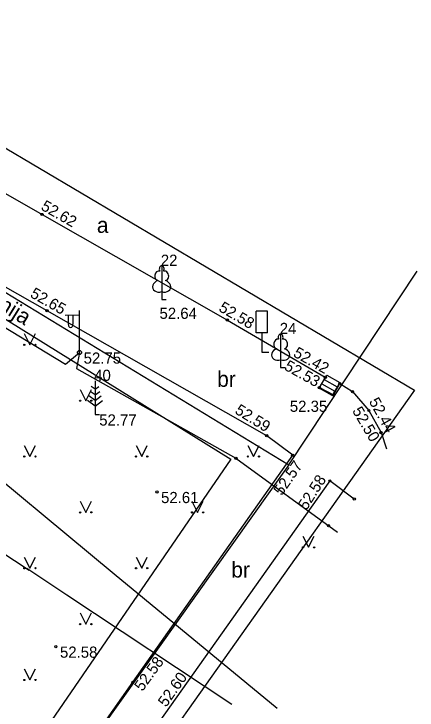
# Model space of a CAD drawing. Extents: x 619806 to 620082, y 405176 to 405386.
# Drawn here: x 620031.79 to 620049.82, y 405261.15 to 405292.31 of the extents above; entities that cross this region are included whole.
import ezdxf

# ---------------------------------------------------------------- set-up
doc = ezdxf.new("R2010")
doc.units = 0
for name, color, linetype in [('APGR_SARK_####_####_#', 7, 'Continuous'), ('APGR_SARK_IZNL_TKST_#', 7, 'Continuous'), ('APGS_ELEM_####_####_#', 7, 'Continuous'), ('APGS_VADP_ZSPR_####_#', 7, 'Continuous'), ('CELI_CAPM_####_####_#', 7, 'Continuous'), ('CELI_CMAL_####_####_#', 7, 'Continuous'), ('CELI_CSEG_####_TKST_#', 7, 'Continuous'), ('CELI_ELEM_####_####_#', 7, 'Continuous'), ('LKAN_ELEM_####_####_#', 7, 'Continuous'), ('LKAN_ELEM_PAST_TKST_#', 7, 'Continuous'), ('RAMI_UZMR_####_####_#', 7, 'Continuous'), ('RELJ_AATZ_####_TKST_#', 7, 'Continuous'), ('RELJ_ELEM_####_####_#', 7, 'Continuous'), ('ROBZ_PROJ_####_####_#', 7, 'Continuous'), ('ROBZ_UZMR_####_####_#', 7, 'Continuous'), ('SAKT_VADP_KABE_####_#', 7, 'Continuous'), ('TERT_DIAM_####_TKST_#', 7, 'Continuous'), ('TERT_ELEM_####_####_#', 7, 'Continuous'), ('UDTK_VADP_UDEN_####_#', 7, 'Continuous')]:
    doc.layers.add(name, color=color, linetype=linetype)

msp = doc.modelspace()

# ---------------------------------------------------------------- linework, layer by layer
at = {"layer": 'APGR_SARK_####_####_#'}
msp.add_lwpolyline([(619976.198, 405343.424), (619987.786, 405326.116), (620001.138, 405307.928), (620014.265, 405290.061), (620015.405, 405288.784), (620016.767, 405287.746), (620041.487, 405272.379), (619990.053, 405197.403), (619990.053, 405197.403)], dxfattribs=at)
at = {"layer": 'APGS_ELEM_####_####_#'}
for p, q in [((620034.718, 405277.157), (620034.718, 405279.04)), ((620034.718, 405278.824), (620034.083, 405278.819)), ((620034.218, 405278.82), (620034.218, 405278.428)), ((620034.428, 405278.822), (620034.428, 405278.428))]:
    msp.add_line(p, q, dxfattribs=at)
msp.add_circle((620034.718, 405277.157), 0.09, dxfattribs=at)
msp.add_ellipse((620034.323, 405278.428), major_axis=(0, 0.151), ratio=0.695971, start_param=1.570796, end_param=4.712389, dxfattribs=at)
at = {"layer": 'APGS_VADP_ZSPR_####_#'}
msp.add_lwpolyline([(619990.647, 405321.492), (619992.044, 405320.41), (619998.442, 405311.177), (620006.316, 405300.184), (620012.827, 405290.604), (620013.926, 405290.046), (620013.66, 405289.472), (620014.139, 405289.916), (620020.167, 405285.36), (620029.979, 405279.119), (620034.093, 405276.637), (620034.718, 405277.157), (620034.581, 405276.433), (620041.718, 405272.423), (620046.265, 405269.109)], dxfattribs=at)
at = {"layer": 'CELI_CAPM_####_####_#'}
msp.add_lwpolyline([(620015.066, 405292.395), (620017.489, 405291.013), (620019.645, 405290.895), (620021.702, 405289.826), (620033.044, 405283.335), (620041.336, 405278.607), (620045.71, 405276.047), (620045.451, 405275.586), (620046.08, 405275.258), (620046.363, 405275.764), (620046.931, 405275.406), (620047.659, 405274.561), (620048.206, 405273.573), (620048.444, 405272.838)], dxfattribs=at)
at = {"layer": 'CELI_CMAL_####_####_#'}
for points in [[(620044.255, 405272.554), (620043.092, 405273.429), (620033.269, 405279.026), (620025.28, 405283.562), (620015.248, 405289.312), (620013.524, 405289.938), (620004.396, 405283.537), (619995.598, 405277.461), (619983.971, 405269.299), (619977.275, 405264.531), (619978.155, 405255.368), (619978.832, 405249.941), (619981.369, 405226.774)], [(620017.253, 405234.372), (620024.304, 405244.304), (620030.33, 405252.781), (620037.106, 405262.397), (620044.255, 405272.554)], [(620047.008, 405270.595), (620045.914, 405271.411), (620038.491, 405260.919), (620032.163, 405251.981), (620025.649, 405242.786), (620018.938, 405233.375), (620011.736, 405223.226), (620012.557, 405222.608)]]:
    msp.add_lwpolyline(points, dxfattribs=at)
at = {"layer": 'CELI_ELEM_####_####_#'}
for p, q in [((620043.124, 405279.013), (620042.624, 405279.013)), ((620042.624, 405278.044), (620042.624, 405279.013)), ((620043.124, 405278.044), (620043.124, 405279.013)), ((620043.124, 405278.044), (620042.624, 405278.044)), ((620042.878, 405278.044), (620042.878, 405277.166)), ((620042.878, 405277.166), (620043.193, 405277.166))]:
    msp.add_line(p, q, dxfattribs=at)
at = {"layer": 'LKAN_ELEM_####_####_#'}
for p, q in [((620045.664, 405275.953), (620046.247, 405275.614)), ((620045.551, 405275.758), (620046.134, 405275.419))]:
    msp.add_line(p, q, dxfattribs=at)
msp.add_lwpolyline([(620045.438, 405275.564), (620045.777, 405276.147), (620046.36, 405275.808), (620046.021, 405275.225)], close=True, dxfattribs=at)
at = {"layer": 'RAMI_UZMR_####_####_#'}
msp.add_lwpolyline([(619874.687, 405324.979), (619926.719, 405349.544), (619966.669, 405369.042), (620021.738, 405292.03), (620049.703, 405275.476), (620026.189, 405242.287), (620012.147, 405222.917), (619996.603, 405200.928), (619989.997, 405199.173), (619982.328, 405199.155), (619922.669, 405233.014), (619882.137, 405255.756), (619859.084, 405268.056), (619820.646, 405290.715), (619813.744, 405295.206), (619820.645, 405298.752)], close=True, dxfattribs=at)
at = {"layer": 'RELJ_ELEM_####_####_#'}
for centre in [(620033.044, 405283.335), (620033.269, 405279.026), (620041.336, 405278.607), (620045.71, 405276.047), (620045.451, 405275.586), (620046.363, 405275.764), (620046.08, 405275.258), (620046.931, 405275.406), (620047.659, 405274.561), (620043.092, 405273.429), (620048.206, 405273.573), (620041.718, 405272.423), (620044.255, 405272.554), (620045.914, 405271.411), (620038.181, 405270.916), (620047.008, 405270.595), (620045.857, 405269.406), (620033.66, 405263.995), (620037.106, 405262.397)]:
    msp.add_circle(centre, 0.05, dxfattribs=at)
at = {"layer": 'ROBZ_PROJ_####_####_#'}
msp.add_line((620044.084, 405272.127), (620049.817, 405280.803), dxfattribs=at)
at = {"layer": 'ROBZ_UZMR_####_####_#'}
for p, q in [((620014.119, 405290.38), (620044.084, 405272.127)), ((620044.084, 405272.127), (619994.191, 405202.148))]:
    msp.add_line(p, q, dxfattribs=at)
at = {"layer": 'SAKT_VADP_KABE_####_#'}
msp.add_lwpolyline([(619935.629, 405357.201), (619939.538, 405347.363), (619973.032, 405319.457), (620006.975, 405291.595), (620036.262, 405267.248), (620043.553, 405261.241)], dxfattribs=at)
at = {"layer": 'TERT_ELEM_####_####_#'}
for p, q in [((620038.395, 405279.882), (620038.395, 405279.535)), ((620038.395, 405279.535), (620038.595, 405279.535)), ((620032.25, 405278), (620032.5, 405277.5)), ((620032.5, 405277.5), (620032.75, 405278)), ((620043.715, 405276.83), (620043.715, 405276.483)), ((620043.715, 405276.483), (620043.915, 405276.483)), ((620035.415, 405275.886), (620035.415, 405274.386)), ((620035.415, 405275.51), (620035.239, 405275.638)), ((620035.415, 405275.51), (620035.589, 405275.638)), ((620034.75, 405275.5), (620035, 405275)), ((620035, 405275), (620035.25, 405275.5)), ((620035.415, 405275.01), (620035.137, 405275.214)), ((620035.415, 405275.26), (620035.199, 405275.418)), ((620035.415, 405275.26), (620035.631, 405275.418)), ((620035.415, 405275.01), (620035.693, 405275.214)), ((620035.415, 405274.76), (620035.083, 405275.004)), ((620035.415, 405274.76), (620035.749, 405275.004)), ((620035.415, 405274.386), (620035.615, 405274.386)), ((620032.25, 405273), (620032.5, 405272.5)), ((620032.5, 405272.5), (620032.75, 405273)), ((620037.25, 405273), (620037.5, 405272.5)), ((620037.5, 405272.5), (620037.75, 405273)), ((620042.25, 405273), (620042.5, 405272.5)), ((620042.5, 405272.5), (620042.75, 405273)), ((620034.75, 405270.5), (620035, 405270)), ((620035, 405270), (620035.25, 405270.5)), ((620039.75, 405270.5), (620040, 405270)), ((620040, 405270), (620040.25, 405270.5)), ((620044.714, 405268.937), (620044.964, 405268.437)), ((620044.964, 405268.437), (620045.214, 405268.937)), ((620032.25, 405268), (620032.5, 405267.5)), ((620032.5, 405267.5), (620032.75, 405268)), ((620037.25, 405268), (620037.5, 405267.5)), ((620037.5, 405267.5), (620037.75, 405268)), ((620034.75, 405265.5), (620035, 405265)), ((620035, 405265), (620035.25, 405265.5)), ((620032.25, 405263), (620032.5, 405262.5)), ((620032.5, 405262.5), (620032.75, 405263))]:
    msp.add_line(p, q, dxfattribs=at)
for points in [[(620038.395, 405281.035), (620038.395, 405279.882)], [(620038.485, 405280.803), (620038.484, 405280.804)], [(620043.715, 405277.983), (620043.715, 405276.83)], [(620043.805, 405277.751), (620043.804, 405277.752)]]:
    msp.add_lwpolyline(points, dxfattribs=at)
for centre, radius in [((620032.25, 405277.5), 0.028), ((620032.75, 405277.5), 0.0263), ((620034.75, 405275), 0.028), ((620035.25, 405275), 0.0263), ((620032.25, 405272.5), 0.028), ((620032.75, 405272.5), 0.0263), ((620037.25, 405272.5), 0.028), ((620037.75, 405272.5), 0.0263), ((620042.25, 405272.5), 0.028), ((620042.75, 405272.5), 0.0263), ((620034.75, 405270), 0.028), ((620035.25, 405270), 0.0263), ((620039.75, 405270), 0.028), ((620040.25, 405270), 0.0263), ((620044.714, 405268.436), 0.028), ((620045.214, 405268.436), 0.0263), ((620032.25, 405267.5), 0.028), ((620032.75, 405267.5), 0.0263), ((620037.25, 405267.5), 0.028), ((620037.75, 405267.5), 0.0263), ((620034.75, 405265), 0.028), ((620035.25, 405265), 0.0263), ((620032.25, 405262.5), 0.028), ((620032.75, 405262.5), 0.0263)]:
    msp.add_circle(centre, radius, dxfattribs=at)
for centre, major_axis, ratio, start_param, end_param in [((620038.267, 405280.59), (-0.039, -0.212), 0.861323, 3.141593, 6.283185), ((620038.395, 405280.885), (0, -0.15), 0.707107, 3.14537, 5.287485), ((620038.395, 405280.885), (0, -0.15), 0.707107, 0.995701, 3.137816), ((620038.523, 405280.59), (0.039, -0.212), 0.861323, 0, 3.141593), ((620038.305, 405280.128), (0.307, 0.095), 0.814445, 1.570796, 4.752015), ((620038.485, 405280.128), (-0.307, 0.095), 0.814445, 1.531171, 4.712389), ((620043.587, 405277.538), (-0.039, -0.212), 0.861323, 3.141593, 6.283185), ((620043.715, 405277.833), (0, -0.15), 0.707107, 3.14537, 5.287485), ((620043.715, 405277.833), (0, -0.15), 0.707107, 0.995701, 3.137816), ((620043.843, 405277.538), (0.039, -0.212), 0.861323, 0, 3.141593), ((620043.625, 405277.076), (0.307, 0.095), 0.814445, 1.570796, 4.752015), ((620043.805, 405277.076), (-0.307, 0.095), 0.814445, 1.531171, 4.712389)]:
    msp.add_ellipse(centre, major_axis=major_axis, ratio=ratio, start_param=start_param, end_param=end_param, dxfattribs=at)
at = {"layer": 'UDTK_VADP_UDEN_####_#'}
for points in [[(620006.936, 405294.332), (620021.003, 405274.963), (620032.468, 405267.412)], [(620041.534, 405261.399), (620034.154, 405266.302), (620032.36, 405267.483)]]:
    msp.add_lwpolyline(points, dxfattribs=at)

# ---------------------------------------------------------------- texts
at = {"layer": 'APGR_SARK_IZNL_TKST_#'}
msp.add_text('sark.līnija', height=0.7, rotation=328.134, dxfattribs=at).set_placement((620028.914, 405280.442))
at = {"layer": 'CELI_CSEG_####_TKST_#'}
for s, p in [('a', (620035.495, 405282.511)), ('br', (620040.876, 405275.619)), ('br', (620041.508, 405267.085))]:
    msp.add_text(s, height=0.7, dxfattribs=at).set_placement(p)
at = {"layer": 'LKAN_ELEM_PAST_TKST_#'}
msp.add_text(' 52.35', height=0.5, dxfattribs=at).set_placement((620043.941, 405274.499))
at = {"layer": 'RELJ_AATZ_####_TKST_#'}
for s, rotation, p in [(' 52.62', 330.3087, (620032.796, 405283.662)), (' 52.65', 330.3261, (620032.313, 405279.753)), (' 52.58', 329.6606, (620040.748, 405279.13)), (' 52.42', 330.6354, (620044.08, 405277.093)), (' 52.53', 330.7118, (620043.676, 405276.501)), (' 52.44', 298.9708, (620047.56, 405275.13)), (' 52.59', 328.2229, (620041.476, 405274.552)), (' 52.50', 300.523, (620046.805, 405274.709)), (' 52.57', 55.0491, (620043.66, 405270.565)), (' 52.58', 57.1892, (620044.771, 405269.912)), (' 52.58', 54.0012, (620037.422, 405261.808)), (' 52.60', 54.7209, (620038.487, 405261.102))]:
    msp.add_text(s, height=0.5, rotation=rotation, dxfattribs=at).set_placement(p)
for s, p in [(' 52.64', (620038.112, 405278.661)), (' 52.75', (620034.718, 405276.657)), (' 52.77', (620035.415, 405273.886)), (' 52.61', (620038.181, 405270.416)), (' 52.58', (620033.66, 405263.495))]:
    msp.add_text(s, height=0.5, dxfattribs=at).set_placement(p)
at = {"layer": 'TERT_DIAM_####_TKST_#'}
for s, p in [(' 22', (620038.17, 405281.035)), (' 24', (620043.49, 405277.983)), (' 40', (620035.19, 405275.886))]:
    msp.add_text(s, height=0.5, dxfattribs=at).set_placement(p)

doc.saveas('drawing.dxf')
